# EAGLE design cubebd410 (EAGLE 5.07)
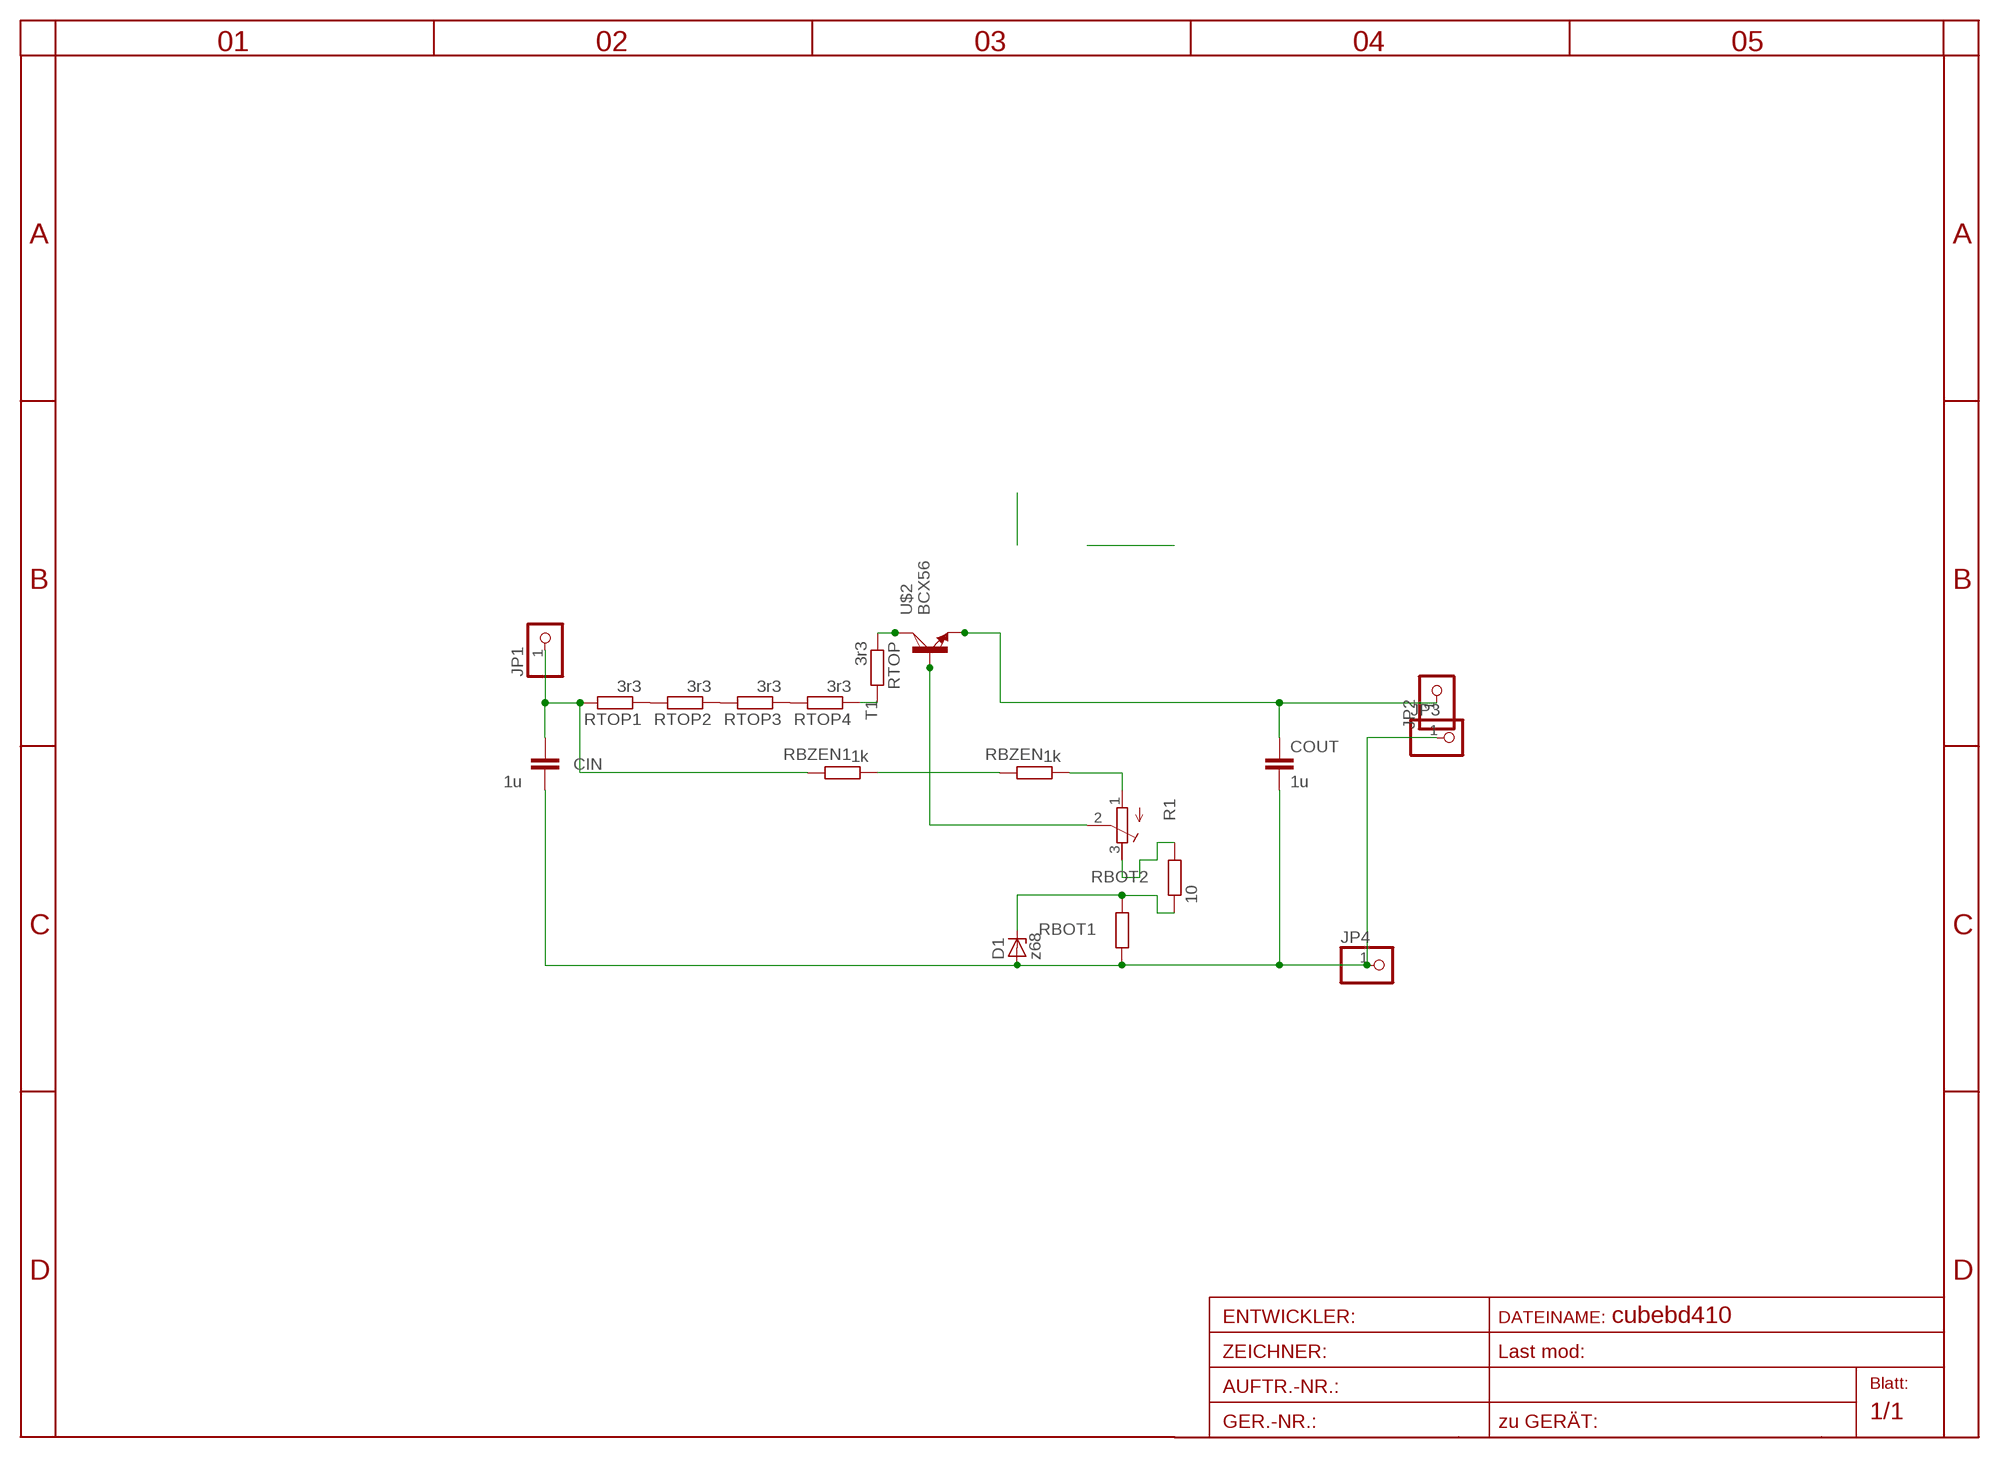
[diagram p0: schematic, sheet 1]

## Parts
CIN  1u  C-EU025-024X044  [C025-024X044]
COUT  1u  C-EU025-024X044  [C025-024X044]
D1  z68  ZENER-DIODESOD80C  [SOD80C]
JP1  PINHD-1X11X0.4  [1X01]
JP2  PINHD-1X11X0.4  [1X01]
JP3  PINHD-1X11X0.4  [1X01]
JP4  PINHD-1X11X0.4  [1X01]
R1  R-TRIMM3202  [RTRIM3202]
RBOT1  R-EU_R0805  [R0805]
RBOT2  10  R-EU_R0805  [R0805]
RBZEN  1k  R-EU_0204/2V  [0204V]
RBZEN1  1k  R-EU_0204/2V  [0204V]
RTOP  3r3  R-EU_0204/2V  [0204V]
RTOP1  3r3  R-EU_0204/2V  [0204V]
RTOP2  3r3  R-EU_0204/2V  [0204V]
RTOP3  3r3  R-EU_0204/2V  [0204V]
RTOP4  3r3  R-EU_0204/2V  [0204V]
T1  -NPN-TO126V  [TO126V]
U$2  BCX56  [SOT223]

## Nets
C: RTOP.1 T1.2(C) U$2.2(C)
GND: CIN.2 COUT.2 D1.A JP3.1 JP4.1 RBOT1.1
N$1: RBZEN1.1 RBZEN.2
N$2: RTOP1.1 RTOP2.2
N$4: R1.3(A) RBOT2.2
N$5: D1.C RBOT1.2 RBOT2.1
N$7: RTOP2.1 RTOP3.2
N$8: RTOP3.1 RTOP4.2
N$9: R1.2(S) T1.3(B) U$2.1(B)
N$10: R1.1(E) RBZEN.1
N$11: RTOP4.1 RTOP.2
OUT: COUT.1 JP2.1 T1.1(E) U$2.3(E)
VPLUS: CIN.1 JP1.1 RBZEN1.2 RTOP1.2

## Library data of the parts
CIN COUT = rcl:C-EU: CAPACITOR, European symbol
D1 = diode:ZENER-DIODE: Z-Diode
JP1-JP4 = pinhead:PINHD-1X1: PIN HEADER
R1 = rcl:R-TRIMM: Trimm resistor
RBOT1 RBOT2 RBZEN RBZEN1 RTOP RTOP1-RTOP4 = rcl:R-EU_: RESISTOR, European symbol
T1 = transistor:*-NPN-: NPN Transistror BF959 corrected 2008.03.06
U$2 = transistor-power:BCX56

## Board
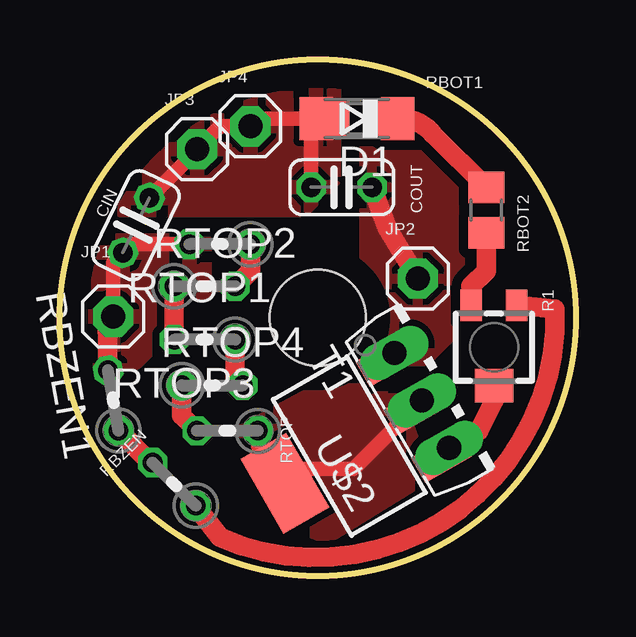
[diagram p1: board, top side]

Size 21.5 x 21.5 mm. Coordinates in mm from the lower left corner, seen from the top.
Outline: circle at 10.75,10.75 radius 10.75
Copper layers (1*16): Top 0.035mm / dielectric 1.5mm / Bottom 0.035mm
Design rules "default *": minimum track width 10mil, minimum drill 20mil, track to track 8mil, track to pad 8mil, pad to pad 8mil, via to via 8mil, smd to smd 8mil, copper to edge 40mil, drill to drill 8mil, minimum pad ring 1mil, minimum via ring 8mil, stop-mask expansion 4mil, vias tented up to drill 0mil, thermal gap 10mil
Holes 4 mm at 10.75,10.75

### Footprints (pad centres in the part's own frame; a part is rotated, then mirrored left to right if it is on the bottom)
C025-024X044 = drill 0.813 octagon: 1 -1.27,0; 2 1.27,0
SOD80C = smd 1.4 x 1.8: A 1.7,0; C -1.7,0
1X01 = drill 1 pad 1.676 octagon: 1 0,0
RTRIM3202 = smd 0.9 x 1.3: 1 -0.95,-1.75; 3 0.95,-1.75 | smd 1.6 x 1.4: 2 0,1.6
R0805 = smd 1.3 x 1.5: 1 -0.95,0; 2 0.95,0
0204V = drill 0.813 octagon: 1 -1.27,0; 2 1.27,0
TO126V = drill 1.016 long: 1 -2.286,-1.27; 2 0,-1.27; 3 2.286,-1.27
SOT223 = smd 1.219 x 2.235: 1 -2.311,-3.099; 2 0,-3.099; 3 2.311,-3.099 | smd 3.6 x 2.2: 4 0,3.099

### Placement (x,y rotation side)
CIN  3.17,14.61 64.2 top
COUT  11.75,16.19 180 top
D1  12.38,19.05 180 top
JP1  2.22,10.79 0 top
JP2  14.92,12.38 0 top
JP3  5.71,17.78 0 top
JP4  7.94,18.73 0 top
R1  18.1,9.53 180 top
RBOT1  12.38,19.05 0 top
RBOT2  17.78,15.24 270 top
RBZEN  4.76,3.81 135 top
RBZEN1  2.22,7.3 100 top
RTOP  6.99,6.03 180 top
RTOP1  6.67,13.82 180 top
RTOP2  6.03,12.06 0 top
RTOP3  6.03,9.84 180 top
RTOP4  6.35,7.94 0 top
T1  16.19,7.94 300 top
U$2  12.06,5.4 120 top

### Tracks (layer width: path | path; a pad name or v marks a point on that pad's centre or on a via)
C
  Top 0.61: T1.2 U$2.2 12.25,4.45 9.21,4.45 8.26,5.4 RTOP.1
  pour Top (isolate 0.305, rank 2): 13.97,7.62 11.75,8.26 7.62,6.03 8.89,2.54 11.11,1.59 15.24,4.13
GND
  Top 0.61: CIN.2 5.71,17.74 JP3.1 6.67,18.73 JP4.1 8.26,19.05 D1.A 10.48,18.84 COUT.2
  Top 0.813: D1.A RBOT1.1
  pour Top (isolate 0.305, rank 2): 2.54,15.24 2.54,16.51 6.35,20.32 11.43,20.32 11.43,16.51 10.16,15.24 5.08,15.24
N$1
  Top 0.813: RBZEN.2 3.79,4.71 RBZEN1.1
N$2
  Top 0.813: RTOP1.1 7.94,12.7 RTOP2.2
N$4
  Top 0.813: RBOT2.2 17.78,12.7 17.14,12.06 R1.3
N$5
  Top 0.813: RBOT2.1 15.56,18.41 arc55 D1.C RBOT1.2
N$7
  Top 0.813: RTOP3.2 RTOP2.1
N$8
  Top 0.813: RTOP3.1 7.3,8.26 RTOP4.2
N$9
  Top 0.61: 16.19,5.23 16.24,5.28 T1.3
  Top 0.813: R1.2 18.09,7.29 17.46,6.03 16.19,5.08 16.19,5.23 U$2.1
N$10
  Top 0.813: RBZEN.1 6.67,1.59 arc116 20.64,11.11 R1.1
N$11
  Top 0.813: RTOP4.1 5.08,6.67 RTOP.2
OUT
  Top 0.61: U$2.3 13.93,9.28 T1.1
  Top 0.813: JP2.1 13.65,14.47 COUT.1
  pour Top (isolate 0.406, rank 3): 12.7,19.05 15.24,19.05 17.78,16.51 17.78,11.43 15.24,8.89 12.7,8.89 12.7,13.97
VPLUS
  Top 0.61: 1.97,10.55 JP1.1 2.22,13.06 CIN.1 2.98,13.82 RTOP1.2
  Top 0.813: RBZEN1.2 1.97,10.55
  pour Top (isolate 0.305): 1.27,8.89 1.27,13.97 6.03,13.97 6.03,13.65 6.03,11.75 3.17,8.89

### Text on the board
tStop: MICHAEL5.net
bStop: MICHAEL5.net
